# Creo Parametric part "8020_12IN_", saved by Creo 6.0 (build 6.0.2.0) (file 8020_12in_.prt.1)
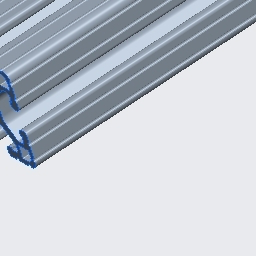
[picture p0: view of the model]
Units: Inch lbm Second (Pro/E Default); INCH, POUND, SECS

Created from: INLBS_PART_SOLID.PRT

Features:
  1. datum plane "RIGHT"
  2. datum plane "TOP"
  3. datum plane "FRONT"
  4. coordinate system
  5. curve "Project 1"
  6. sketch "Sketch 2"
  7. extrusion "Extrude 1"

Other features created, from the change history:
  sketch "Sketch 1"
